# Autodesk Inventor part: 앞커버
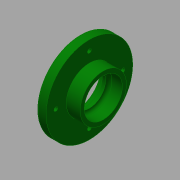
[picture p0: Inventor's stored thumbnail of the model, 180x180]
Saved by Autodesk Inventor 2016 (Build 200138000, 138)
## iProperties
Created: 2015-09
Part Number: 앞커버
Material: 알루미늄 6061
Document SubType Name: Modeling
Designer: mduedu
Density: 2.71 g/cm^3
Mass: 58.9874 g
Surface Area: 98.7754 cm^2
Volume: 21.7666 cm^3
Appearance: 진녹색
Author: mduedu
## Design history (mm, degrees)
sketch "스케치1"
  geometry: L1 (-4, 67)-(-16, 67); L2 (-16, 67)-(-16, 84.5); L3 (-16, 84.5)-(-24, 84.5); L4 (-24, 84.5)-(-24, 70.5); L5 (-27, 70.5)-(-27, 61); L6 (-27, 61)-(-4, 61); L7 (-4, 61)-(-4, 67); L8 (-79.5, 39.5)-(-79.5, 54.5) reference; L9 (48.5, 54.5)-(48.5, 39.5) reference; L10 (-79.5, 47)-(48.5, 47); L11 (-24, 70.5)-(-27, 70.5); 3 further points
  constraints: 18 end point, 6 parallel, 4 midpoint, 1 horizontal, 1 perpendicular, 1 vertical alignment
  dimensions: "d0" = 23 distance between parallel lines of L7 L5; "d2" = 28 diameter of L6 L10; "d3" = 40 diameter of L1 L10; "d5" = 12 distance of L1.start L1.end; "d6" = 75 diameter of L3 L10; "d7" = 8 distance of L2.end L3.end; "d8" = 47 diameter of L4.end L10
revolve "회전1" sketch "스케치1" stored, may be unused: angle "d4" = 90 deg
sketch "스케치2"
  geometry: C1 r 37.5 at (0, 0) reference; 2 further points
  constraints: 1 coincident
hole "구멍1" sketch "스케치2" at (0, 0) diameter "d11" = 33; stored, may be unused: countersink angle "d15" = 90 deg, drill point angle "d17" = 0 deg; dims "d12" = 6, "d13" = 4, "d14" = 2, "d16" = 12
fillet "모깎기1" dims "d18" = 3
fillet "모깎기2" dims "d19" = 1
sketch "스케치3"
  geometry: C1 r 37.5 at (0, 0) reference; 2 further points
  constraints: 1 coincident
hole "구멍2" sketch "스케치3" at (0, 0) diameter "d20" = 40; stored, may be unused: countersink angle "d24" = 90 deg, drill point angle "d26" = 0 deg; dims "d21" = 6, "d22" = 4, "d23" = 2, "d25" = 8
fillet "모깎기3" dims "d27" = 0.4
chamfer "모따기1" distance "d28" = 1; stored, may be unused: second distance "d29" = 2, angle "d30" = 30 deg
sketch "스케치7" dims "d56" = 58
  geometry: C1 r 37.5 at (0, 0) reference; 5 further points
  constraints: 2 vertical alignment, 1 coincident, 7 other
  dimensions: "d59" = 360 deg dimension on C1.centre point (0, 29) (derived)
hole "구멍4" sketch "스케치7" at (0, 29), (-29, 0), (0, -29), (29, 0) diameter "d48" = 3.4; stored, may be unused: countersink angle "d52" = 90 deg, drill point angle "d54" = 0 deg; dims "d49" = 6, "d50" = 6.5, "d51" = 3.4, "d53" = 8
node "솔리드1"
node "참조1"
node "참조2"
